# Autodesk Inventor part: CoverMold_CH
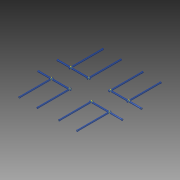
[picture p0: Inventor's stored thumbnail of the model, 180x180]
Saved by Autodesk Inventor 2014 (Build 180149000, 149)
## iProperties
Created: 2009-12
Part Number: CoverMold_CH
Document SubType Name: Modeling
Designer: gaom
Density: 1 g/cm^3
Material: Generic
Appearance: Clear - Blue
Author: gaom
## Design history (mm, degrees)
workplane "Work Plane1"
node "Cooling Segment1"
  sketch "Sketch1"
    geometry: L1 (0, 0)-(0, -6.87); L2 (0, -6.87)-(10.02, -6.244); L3 (10.02, -6.244)-(10.02, -5.75); L4 (10.02, -5.75)-(271.5, -5.75); L5 (271.5, -5.75)-(274.955, 0); L6 (274.955, 0)-(260, 0); L7 (0, 0)-(260, 0)
    constraints: 14 end point, 2 perpendicular, 1 collinear, 1 parallel
    dimensions: "d0" = 5.75 distance between parallel lines of L4 L7; "d1" = 14.95495 distance of L5.end L6.end; "d2" = 10.0203 distance between parallel lines of L3 L1; "d3" = 93.5763 deg angle of L2 L3; "d4" = 0.4937 distance of L2.end L3.end; "d5" = 59 deg angle of L5 L7
  workpoint "Work Point1"
  workaxis "Work Axis1"
workplane "Work Plane2"
node "Cooling Segment2"
  sketch "Sketch2"
    geometry: L1 (0, 0)-(0, -6.87); L2 (0, -6.87)-(10.02, -6.244); L3 (10.02, -6.244)-(10.02, -5.75); L4 (10.02, -5.75)-(271.5, -5.75); L5 (271.5, -5.75)-(274.955, 0); L6 (274.955, 0)-(260, 0); L7 (0, 0)-(260, 0)
    constraints: 14 end point, 2 perpendicular, 1 collinear, 1 parallel
    dimensions: "d8" = 5.75 distance between parallel lines of L4 L7; "d9" = 14.95495 distance of L5.end L6.end; "d10" = 10.0203 distance between parallel lines of L3 L1; "d11" = 93.5763 deg angle of L2 L3; "d12" = 0.4937 distance of L2.end L3.end; "d13" = 59 deg angle of L5 L7
  workpoint "Work Point2"
  workaxis "Work Axis2"
workplane "Work Plane3"
node "Cooling Segment3"
  sketch "Sketch3"
    geometry: L1 (0, 0)-(0, -6.87); L2 (0, -6.87)-(10.02, -6.244); L3 (10.02, -6.244)-(10.02, -5.75); L4 (10.02, -5.75)-(271.5, -5.75); L5 (271.5, -5.75)-(274.955, 0); L6 (274.955, 0)-(260, 0); L7 (0, 0)-(260, 0)
    constraints: 14 end point, 2 perpendicular, 1 collinear, 1 parallel
    dimensions: "d16" = 5.75 distance between parallel lines of L4 L7; "d17" = 14.95495 distance of L5.end L6.end; "d18" = 10.0203 distance between parallel lines of L3 L1; "d19" = 93.5763 deg angle of L2 L3; "d20" = 0.4937 distance of L2.end L3.end; "d21" = 59 deg angle of L5 L7
  workpoint "Work Point3"
  workaxis "Work Axis3"
workplane "Work Plane4"
node "Cooling Segment4"
  sketch "Sketch4"
    geometry: L1 (0, 0)-(0, -6.87); L2 (0, -6.87)-(10.02, -6.244); L3 (10.02, -6.244)-(10.02, -5.75); L4 (10.02, -5.75)-(271.5, -5.75); L5 (271.5, -5.75)-(274.955, 0); L6 (274.955, 0)-(260, 0); L7 (0, 0)-(260, 0)
    constraints: 14 end point, 2 perpendicular, 1 collinear, 1 parallel
    dimensions: "d24" = 5.75 distance between parallel lines of L4 L7; "d25" = 14.95495 distance of L5.end L6.end; "d26" = 10.0203 distance between parallel lines of L3 L1; "d27" = 93.5763 deg angle of L2 L3; "d28" = 0.4937 distance of L2.end L3.end; "d29" = 59 deg angle of L5 L7
  workpoint "Work Point4"
  workaxis "Work Axis4"
workplane "Work Plane5"
node "Cooling Segment5"
  sketch "Sketch5"
    geometry: L1 (0, 0)-(0, -6.87); L2 (0, -6.87)-(10.02, -6.244); L3 (10.02, -6.244)-(10.02, -5.75); L4 (10.02, -5.75)-(279.5, -5.75); L5 (279.5, -5.75)-(282.955, 0); L6 (282.955, 0)-(268, 0); L7 (0, 0)-(268, 0)
    constraints: 14 end point, 2 perpendicular, 1 collinear, 1 parallel
    dimensions: "d32" = 5.75 distance between parallel lines of L4 L7; "d33" = 14.95495 distance of L5.end L6.end; "d34" = 10.0203 distance between parallel lines of L3 L1; "d35" = 93.5763 deg angle of L2 L3; "d36" = 0.4937 distance of L2.end L3.end; "d37" = 59 deg angle of L5 L7
  workpoint "Work Point5"
  workaxis "Work Axis5"
workplane "Work Plane6"
node "Cooling Segment6"
  sketch "Sketch6"
    geometry: L1 (0, 0)-(0, -6.87); L2 (0, -6.87)-(10.02, -6.244); L3 (10.02, -6.244)-(10.02, -5.75); L4 (10.02, -5.75)-(279.5, -5.75); L5 (279.5, -5.75)-(282.955, 0); L6 (282.955, 0)-(268, 0); L7 (0, 0)-(268, 0)
    constraints: 14 end point, 2 perpendicular, 1 collinear, 1 parallel
    dimensions: "d40" = 5.75 distance between parallel lines of L4 L7; "d41" = 14.95495 distance of L5.end L6.end; "d42" = 10.0203 distance between parallel lines of L3 L1; "d43" = 93.5763 deg angle of L2 L3; "d44" = 0.4937 distance of L2.end L3.end; "d45" = 59 deg angle of L5 L7
  workpoint "Work Point6"
  workaxis "Work Axis6"
workplane "Work Plane7"
node "Cooling Segment7"
  sketch "Sketch7"
    geometry: L1 (0, 0)-(0, -6.87); L2 (0, -6.87)-(10.02, -6.244); L3 (10.02, -6.244)-(10.02, -5.75); L4 (10.02, -5.75)-(279.5, -5.75); L5 (279.5, -5.75)-(282.955, 0); L6 (282.955, 0)-(268, 0); L7 (0, 0)-(268, 0)
    constraints: 14 end point, 2 perpendicular, 1 collinear, 1 parallel
    dimensions: "d48" = 5.75 distance between parallel lines of L4 L7; "d49" = 14.95495 distance of L5.end L6.end; "d50" = 10.0203 distance between parallel lines of L3 L1; "d51" = 93.5763 deg angle of L2 L3; "d52" = 0.4937 distance of L2.end L3.end; "d53" = 59 deg angle of L5 L7
  workpoint "Work Point7"
  workaxis "Work Axis7"
workplane "Work Plane8"
node "Cooling Segment8"
  sketch "Sketch8"
    geometry: L1 (0, 0)-(0, -6.87); L2 (0, -6.87)-(10.02, -6.244); L3 (10.02, -6.244)-(10.02, -5.75); L4 (10.02, -5.75)-(279.5, -5.75); L5 (279.5, -5.75)-(282.955, 0); L6 (282.955, 0)-(268, 0); L7 (0, 0)-(268, 0)
    constraints: 14 end point, 2 perpendicular, 1 collinear, 1 parallel
    dimensions: "d56" = 5.75 distance between parallel lines of L4 L7; "d57" = 14.95495 distance of L5.end L6.end; "d58" = 10.0203 distance between parallel lines of L3 L1; "d59" = 93.5763 deg angle of L2 L3; "d60" = 0.4937 distance of L2.end L3.end; "d61" = 59 deg angle of L5 L7
  workpoint "Work Point8"
  workaxis "Work Axis8"
workplane "Work Plane9"
node "Cooling Segment9"
  sketch "Sketch9"
    geometry: L1 (0, 0)-(0, -6.87); L2 (0, -6.87)-(10.02, -6.244); L3 (10.02, -6.244)-(10.02, -5.75); L4 (10.02, -5.75)-(279.5, -5.75); L5 (279.5, -5.75)-(282.955, 0); L6 (282.955, 0)-(268, 0); L7 (0, 0)-(268, 0)
    constraints: 14 end point, 2 perpendicular, 1 collinear, 1 parallel
    dimensions: "d64" = 5.75 distance between parallel lines of L4 L7; "d65" = 14.95495 distance of L5.end L6.end; "d66" = 10.0203 distance between parallel lines of L3 L1; "d67" = 93.5763 deg angle of L2 L3; "d68" = 0.4937 distance of L2.end L3.end; "d69" = 59 deg angle of L5 L7
  workpoint "Work Point9"
  workaxis "Work Axis9"
workplane "Work Plane10"
node "Cooling Segment10"
  sketch "Sketch10"
    geometry: L1 (0, 0)-(0, -6.87); L2 (0, -6.87)-(10.02, -6.244); L3 (10.02, -6.244)-(10.02, -5.75); L4 (10.02, -5.75)-(279.5, -5.75); L5 (279.5, -5.75)-(282.955, 0); L6 (282.955, 0)-(268, 0); L7 (0, 0)-(268, 0)
    constraints: 14 end point, 2 perpendicular, 1 collinear, 1 parallel
    dimensions: "d72" = 5.75 distance between parallel lines of L4 L7; "d73" = 14.95495 distance of L5.end L6.end; "d74" = 10.0203 distance between parallel lines of L3 L1; "d75" = 93.5763 deg angle of L2 L3; "d76" = 0.4937 distance of L2.end L3.end; "d77" = 59 deg angle of L5 L7
  workpoint "Work Point10"
  workaxis "Work Axis10"
workplane "Work Plane11"
node "Cooling Segment11"
  sketch "Sketch11"
    geometry: L1 (0, 0)-(0, -6.87); L2 (0, -6.87)-(10.02, -6.244); L3 (10.02, -6.244)-(10.02, -5.75); L4 (10.02, -5.75)-(279.5, -5.75); L5 (279.5, -5.75)-(282.955, 0); L6 (282.955, 0)-(268, 0); L7 (0, 0)-(268, 0)
    constraints: 14 end point, 2 perpendicular, 1 collinear, 1 parallel
    dimensions: "d80" = 5.75 distance between parallel lines of L4 L7; "d81" = 14.95495 distance of L5.end L6.end; "d82" = 10.0203 distance between parallel lines of L3 L1; "d83" = 93.5763 deg angle of L2 L3; "d84" = 0.4937 distance of L2.end L3.end; "d85" = 59 deg angle of L5 L7
  workpoint "Work Point11"
  workaxis "Work Axis11"
workplane "Work Plane12"
node "Cooling Segment12"
  sketch "Sketch12"
    geometry: L1 (0, 0)-(0, -6.87); L2 (0, -6.87)-(10.02, -6.244); L3 (10.02, -6.244)-(10.02, -5.75); L4 (10.02, -5.75)-(279.5, -5.75); L5 (279.5, -5.75)-(282.955, 0); L6 (282.955, 0)-(268, 0); L7 (0, 0)-(268, 0)
    constraints: 14 end point, 2 perpendicular, 1 collinear, 1 parallel
    dimensions: "d88" = 5.75 distance between parallel lines of L4 L7; "d89" = 14.95495 distance of L5.end L6.end; "d90" = 10.0203 distance between parallel lines of L3 L1; "d91" = 93.5763 deg angle of L2 L3; "d92" = 0.4937 distance of L2.end L3.end; "d93" = 59 deg angle of L5 L7
  workpoint "Work Point12"
  workaxis "Work Axis12"
body "Solid1"
revolve "Revolution1" stored, may be unused: angle "d6" = 0 deg
body "Srf1"
revolve "Revolution2" stored, may be unused: angle "d14" = 0 deg
body "Srf2"
revolve "Revolution3" stored, may be unused: angle "d22" = 0 deg
body "Srf3"
revolve "Revolution4" stored, may be unused: angle "d30" = 0 deg
body "Srf4"
revolve "Revolution5" stored, may be unused: angle "d38" = 0 deg
body "Srf5"
revolve "Revolution6" stored, may be unused: angle "d46" = 0 deg
body "Srf6"
revolve "Revolution7" stored, may be unused: angle "d54" = 0 deg
body "Srf7"
revolve "Revolution8" stored, may be unused: angle "d62" = 0 deg
body "Srf8"
revolve "Revolution9" stored, may be unused: angle "d70" = 0 deg
body "Srf9"
revolve "Revolution10" stored, may be unused: angle "d78" = 0 deg
body "Srf10"
revolve "Revolution11" stored, may be unused: angle "d86" = 0 deg
body "Srf11"
revolve "Revolution12" stored, may be unused: angle "d94" = 0 deg
body "Srf12"
feature "RevolutionSrf1" dims angle "d7" = 0 deg
feature "RevolutionSrf2" dims angle "d15" = 0 deg
feature "RevolutionSrf3" dims angle "d23" = 0 deg
feature "RevolutionSrf4" dims angle "d31" = 0 deg
feature "RevolutionSrf5" dims angle "d39" = 0 deg
feature "RevolutionSrf6" dims angle "d47" = 0 deg
feature "RevolutionSrf7" dims angle "d55" = 0 deg
feature "RevolutionSrf8" dims angle "d63" = 0 deg
feature "RevolutionSrf9" dims angle "d71" = 0 deg
feature "RevolutionSrf10" dims angle "d79" = 0 deg
feature "RevolutionSrf11" dims angle "d87" = 0 deg
feature "RevolutionSrf12" dims angle "d95" = 0 deg
